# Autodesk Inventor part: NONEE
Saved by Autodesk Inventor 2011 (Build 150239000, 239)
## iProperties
Created: 2007-10
Part Number: NONEE
Document SubType Name: Modeling
Density: 1 g/cm^3
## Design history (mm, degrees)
feature "Base1"
body "Solid1"
